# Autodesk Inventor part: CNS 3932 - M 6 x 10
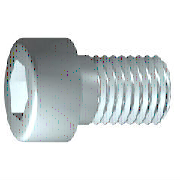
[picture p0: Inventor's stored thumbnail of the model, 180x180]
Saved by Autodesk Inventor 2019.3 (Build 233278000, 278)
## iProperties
Created: 2018-01
Part Number: CNS 3932 - M 6 x 10
Material: Ocel, měkká
Description: Šroub s válcovou hlavou s vnitřním šestihranem
Document SubType Name: Modeling
Standard: CNS 3932
Designer: B-hon
Standards Organization: CNS
Language: cs-CZ
Size Designation: M 6 x 10
Categories: <MemberInstance><Categories><Category DisplayName="Spojovací materiál" InternalName="e4da775c-781d-43d5-af7c-5136215cf5a6" Mnemonic="FSTN"><Category DisplayName
Density: 7.85 g/cm^3
Appearance: Pololeštěná
IsCustomPart: 0
Author: B-hon
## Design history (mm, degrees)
sketch "Náčrt1"
  geometry: L1 (-1.033, 0)-(10, 0); L2 (10, 0)-(10, 3); L3 (10, 3)-(2.5, 3); L4 (2.5, 3)-(1.886, 3); L5 (1.886, 3)-(0, 3); L6 (0, 3)-(0, 5); L7 (0, 5)-(-6, 5); L8 (-6, 5)-(-6, 2.887); L9 (-6, 2.887)-(-2.7, 2.887); L10 (-2.7, 2.887)-(-1.033, 0); L11 (-9.2, 0)-(13.2, 0) reference; L12 (0, -1)-(0, 6) reference; L13 (2.5, 3)-(0, 3)
  constraints: 22 end point, 6 parallel, 2 collinear, 2 perpendicular, 1 horizontal, 1 point on line
  dimensions: "d1" = 7.5 distance from line of L3.end L2 (= GEL); "d2" = 0.61355 distance of L4.end L3.end (computed from GAL); "d3" = 6 distance between parallel lines of L8 L6 (= KOH); "d4" = 3.3 distance of L8.end L9.end (= INTI); "d5" = 60 deg angle of L10 L1; "d6" = 6 diameter of L3 L1 (= GD); "d7" = 6 diameter of L5 L1 (= BDM); "d8" = 5.7735 diameter of L9 L1 (= 1.1547 x SW); "d9" = 10 diameter of L7 L1 (= KOD); "d26" = 10 distance between parallel lines of L12 L2 (= NLG)
revolve "Těleso" sketch "Náčrt1" stored, may be unused: angle "d10" = 90 deg
sketch "Náčrt2"
  geometry: L1 (0, -7)-(0, 7) reference; L2 (-7, 0)-(7, 0) reference; L3 (2.887, 0)-(1.443, -2.5); L4 (1.443, -2.5)-(-1.443, -2.5); L5 (-1.443, -2.5)-(-2.887, 0); L6 (-2.887, 0)-(-1.443, 2.5); L7 (-1.443, 2.5)-(1.443, 2.5); L8 (1.443, 2.5)-(2.887, 0); 2 further points
  constraints: 12 end point, 1 coincident, 1 horizontal alignment, 1 point on line, 12 other
extrude "Drážka" join sketch "Náčrt2" stored distance "d11" = 10; taper "d12" = 0 deg
workplane "Work Plane1"
fillet "Fillet2" dims "d30" = 0.1 (= R)
body "Solid1"
fillet "Zaoblení1" dims "d17" = 0.5 (= RR)
feature "Závit" dims "d13" = 7.5 (= GEL), "d14" = 0
chamfer "Zkosení1" distance "d15" = 0.61345 (= -0.5 x SPD + 0.5 x GD); stored, may be unused: second distance "d16" = 0.61345 (= GUL), angle "d27" = 45 deg
other parameters: "GD" = 6 (= NND) [user parameter; used in 2 equation terms], "NLG" = 10 [user parameter; used in 1 equation term], "GEL" = 7.5 [user parameter; used in 2 equation terms], "KOD" = 10 [user parameter; used in 1 equation term], "KOH" = 6 (= NND) [user parameter; used in 1 equation term], "INTI" = 3.3 [user parameter; used in 1 equation term], "GAL" = 0.61345 (= 0.61345 x PTC) [user parameter; used in 1 equation term], "GUL" = 0.61345 (= 0.61345 x PTC) [user parameter; used in 1 equation term], "BDM" = 6 (= NND) [user parameter; used in 1 equation term], "SW" = 5 [user parameter; used in 2 equation terms], "RR" = 0.5 [user parameter; used in 1 equation term], "SPD" = 4.7731 (= NND - 1.2269 x PTC) [user parameter; used in 1 equation term], "d19" = 0, "d28" = 0, "d29" = 0, "R" = 0.1 [user parameter; used in 1 equation term], "TOA" = 30 deg [user parameter], "GD1" = 4.7731 (= THREADDIA - 1.2269 x PTC) [user parameter], "THREADDIA" = 6 [user parameter; used in 1 equation term], "FAWI" = 45 deg [user parameter], "PTC" = 1 [user parameter; used in 5 equation terms], "NND" = 6 [user parameter; used in 4 equation terms], "E0" = 5.775 (= 1.155 x SW) [user parameter]
